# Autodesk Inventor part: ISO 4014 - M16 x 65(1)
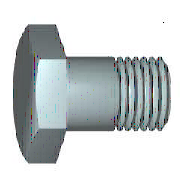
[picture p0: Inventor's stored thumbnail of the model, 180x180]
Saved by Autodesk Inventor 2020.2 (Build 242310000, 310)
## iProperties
Created: 2019-01
Part Number: ISO 4014 - M16 x 65(1)
Material: Edelstahl, 440C
Description: Sechskantschraube
Document SubType Name: Modeling
Standard: DIN EN 24014
Designer: lutzd
Standards Organization: DIN
Language: de-DE
Size Designation: M16 x 65
Categories: <MemberInstance><Categories><Category DisplayName="Verbindungselemente" InternalName="e4da775c-781d-43d5-af7c-5136215cf5a6" Mnemonic="FSTN"><Category DisplayNam
Density: 7.75 g/cm^3
Appearance: Halbpoliert
IsCustomPart: 0
Author: lutzd
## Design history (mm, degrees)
sketch "Skizze1"
  geometry: L1 (0, 11.245)-(0, 8); L2 (27, 8)-(65, 8); L3 (65, 8)-(65, 0); L4 (65, 0)-(-0.8, 0); L5 (-13.96, 0)-(78.16, 0) reference; L6 (-0.8, 0)-(-0.8, 11.245); L7 (-0.8, 11.245)-(0, 11.245); L8 (27, 8)-(25.773, 8); L9 (25.773, 8)-(0, 8); L10 (0, -2.249)-(0, 13.494) reference
  constraints: 16 end point, 2 collinear, 2 perpendicular, 1 parallel
  dimensions: "d0" = 65 distance between parallel lines of L3 L1 (= NLG); "d1" = 38 distance from line of L2.start L3 (= GEL); "d2" = 16 diameter of L2 L4 (= GD); "d9" = 0.8001 distance between parallel lines of L6 L1 (computed from SD); "d10" = 22.49 diameter of L7 L4 (= SD2); "d13" = 1.227 distance of L2.start L8.end (computed from GAL); "d14" = 16 diameter of L9 L4 (= BDM)
revolve "Körper" sketch "Skizze1" stored, may be unused: angle "d12" = 90 deg
sketch "Skizze2"
  geometry: L1 (0, 13.856)-(12, 6.928); L2 (12, 6.928)-(12, -6.928); L3 (12, -6.928)-(0, -13.856); L4 (0, -13.856)-(-12, -6.928); L5 (-12, -6.928)-(-12, 6.928); L6 (-12, 6.928)-(0, 13.856); 2 further points
  constraints: 12 end point, 1 coincident, 1 vertical, 11 other
  dimensions: "d11" = 24 distance between parallel lines of L5 L2 (= SW)
extrude "Kopf" join sketch "Skizze2" distance "d3" = 9.2 (= KOH - SD); taper "d4" = 0 deg
sketch "Skizze4"
  geometry: L1 (-10, 12)-(-10, 13.856); L2 (-10, 13.856)-(-8.928, 13.856); L3 (-8.928, 13.856)-(-10, 12); L4 (-11.84, 0)-(1.04, 0) reference; L5 (-0.8, 13.856)-(-10, 13.856) reference; L6 (-10, 6.928)-(-10, 13.856) reference
  constraints: 6 end point, 2 collinear, 1 perpendicular, 1 vertical
  dimensions: "d5" = 30 deg angle of L3 L1 (= ANG1); "d19" = 24 diameter of L1.start L4 (= SW0)
revolve "Fase1" sketch "Skizze4" stored, may be unused: angle "d21" = 90 deg
workplane "Work Plane1"
body "Solid1"
feature "Gewinde" dims "d15" = 38 (= GEL), "d16" = 0
chamfer "Fase2" distance "d6" = 1.2269 (= -0.5 x SPD + 0.5 x GD); stored, may be unused: second distance "d7" = 1.227 (computed from GUL), angle "d55" = 45 deg
other parameters: "NLG" = 65 [user parameter; used in 1 equation term], "GD" = 16 (= NND) [user parameter; used in 2 equation terms], "BDM" = 16 (= NND) [user parameter; used in 1 equation term], "KOH" = 10 [user parameter; used in 1 equation term], "GEL" = 38 [user parameter; used in 2 equation terms], "SW" = 24 [user parameter; used in 3 equation terms], "SW0" = 24 (= SW) [user parameter; used in 1 equation term], "SPD" = 13.5462 (= NND - 1.2269 x PTC) [user parameter; used in 1 equation term], "SD2" = 22.49 [user parameter; used in 2 equation terms], "SD" = 0.8 [user parameter; used in 2 equation terms], "ANG1" = 30 deg [user parameter; used in 1 equation term], "GAL" = 1.2269 (= 0.61345 x PTC) [user parameter; used in 1 equation term], "GUL" = 1.2269 (= 0.61345 x PTC) [user parameter; used in 1 equation term], "d8" = 0, "RR" = 0.6 [user parameter], "d57" = 0, "d58" = 0, "TPU" = 5 (computed from PTC) [user parameter], "GD1" = 13.5462 (= THREADDIA - 1.2269 x PTC) [user parameter], "THREADDIA" = 16 [user parameter; used in 1 equation term], "SDH" = 22.49 (= SD2) [user parameter], "TOA" = 30 deg [user parameter], "PTC" = 2 [user parameter; used in 5 equation terms], "NND" = 16 [user parameter; used in 3 equation terms], "E0" = 27.72 (= 1.155 x SW) [user parameter]
